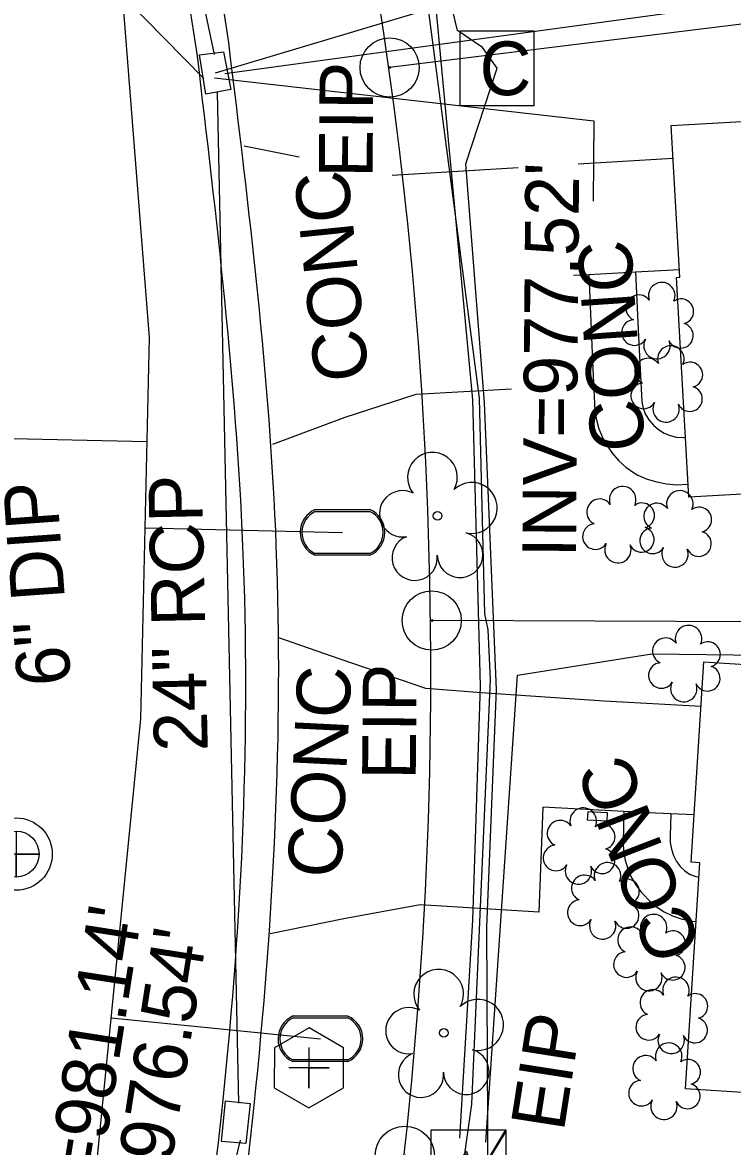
# Model space of a CAD drawing. Extents: x 1614611 to 1617571, y 898867 to 905462.
# Drawn here: x 1616421.9 to 1616474.8, y 901985 to 902068.7 of the extents above; entities that cross this region are included whole.
import ezdxf

# ---------------------------------------------------------------- set-up
doc = ezdxf.new("R2010")
doc.units = 0
for name, color, linetype in [('Exist Boundary Watershed Residential C 05', 7, 'Continuous'), ('Exist Building', 7, 'Continuous'), ('Exist Drainage Structure Drop Inlet CELL', 7, 'Continuous'), ('Exist Other Culture Area Outline', 7, 'Continuous'), ('Exist Other Culture Area Outline Text', 7, 'Continuous'), ('Exist Plan Preparation Watershed Yellow', 7, 'Continuous'), ('Exist Roads EOP Other Text', 7, 'Continuous'), ('Exist Structure Minor Catch Basin Top Elevation', 7, 'Continuous'), ('Exist Structure Minor Pipes RCP 24 Inch Invert', 7, 'Continuous'), ('Exist Utilities Sanitary Sewer UG Line Text', 7, 'Continuous'), ('Exist Utilities Telephone UG FO SUE LOS B', 7, 'Continuous'), ('Exist Utilities TV Pedestal CELL', 7, 'Continuous'), ('Exist Utilities TV UG Cable SUE LOS B', 7, 'Continuous'), ('Exist Utilities Water UG Line SUE LOS B', 7, 'Continuous'), ('Exist Vegetation Shrub CELL', 7, 'Continuous'), ('Exist Vegetation Tree CELL', 7, 'Continuous'), ('Old_Level_21', 7, 'Continuous'), ('Prop Drainage Structure Catch Basin Grate 840 03E Label', 7, 'Continuous'), ('Prop Drainage Structure Catch Basin Open Throat 4 CELL', 7, 'Continuous'), ('Prop Drainage Structure Pipe Alternate 18in Label', 7, 'Continuous'), ('Prop Drainage Structure Pipe Alternate 30in Label', 7, 'Continuous'), ('Prop Drainage Structure Pipe Stub Out CELL', 7, 'Continuous'), ('Prop Earthen Structure Head Ditch Label', 7, 'Continuous'), ('Prop Erosion Embankment Toe Protection CELL', 7, 'Continuous'), ('Prop Erosion Embankment Toe Protection Label', 7, 'Continuous'), ('Prop Erosion Embankment Toe Protection with Rip Rap 3 Detail CELL', 7, 'Continuous'), ('Prop Erosion Rip Rap Class B Label', 7, 'Continuous'), ('Prop Plan Preparation Drainage Notes Label', 7, 'Continuous'), ('Prop Plan Preparation Elevation Label', 7, 'Continuous'), ('Prop SS Transition Line', 7, 'Continuous'), ('Raster_Level_4', 7, 'Continuous'), ('Scratch_Level_1', 7, 'Continuous'), ('Scratch_Level_9', 7, 'Continuous')]:
    doc.layers.add(name, color=color, linetype=linetype)

# ---------------------------------------------------------------- blocks, each defined once
blk = doc.blocks.new('EXIST UTILITIES SANITARY SEWER MANHOLE')
at = {"layer": 'Old_Level_21'}
blk.add_lwpolyline([(0, 0.03425), (0, -0.03425), (0, 0), (0.03425, 0), (-0.03425, 0)], dxfattribs=at)
for radius in [0.05389, 0.03425]:
    blk.add_circle((0, 0), radius, dxfattribs=at)
blk = doc.blocks.new('EXIST PROPERTY IRON PIN')
at = {"layer": 'Exist Plan Preparation Watershed Yellow'}
for radius in [0.0441, 0.00141]:
    blk.add_circle((0, 0), radius, dxfattribs=at)
blk = doc.blocks.new('EXIST UTILITIES SANITARY SEWER CLEAN-OUT')
at = {"layer": 'Prop Drainage Structure Pipe Stub Out CELL'}
blk.add_line((0, 0), (0, 0), dxfattribs=at)
blk.add_lwpolyline([(-0.0516, 0.0299), (-0.0517, -0.0297), (-0.0001, -0.0596), (0.0516, -0.0299), (0.0517, 0.0297), (0.0001, 0.0596)], close=True, dxfattribs=at)
blk.add_lwpolyline([(0, 0.0302), (0, -0.0302), (0, 0), (0.0302, 0), (-0.0302, 0)], dxfattribs=at)
blk = doc.blocks.new('EXIST UTILITIES POWER TRANSFORMER')
at = {"layer": 'Prop Erosion Rip Rap Class B Label'}
blk.add_line((0, 0), (0, 0), dxfattribs=at)
blk.add_lwpolyline([(-0.0569, 0.0522), (0.0542, 0.0522), (0.0542, -0.0588), (-0.0569, -0.0588)], close=True, dxfattribs=at)
for points in [[(-0.0569, -0.0588), (-0.004, 0.0201), (0.0086, -0.0241), (0.0542, 0.0522)], [(-0.0555, -0.0588), (-0.004, 0.0159), (0.0077, -0.0278), (0.0542, 0.0491)]]:
    blk.add_lwpolyline(points, dxfattribs=at)
blk = doc.blocks.new('EXIST UTILITIES WATER METER')
at = {"layer": 'Prop SS Transition Line'}
blk.add_line((0, 0), (0, 0), dxfattribs=at)
for points in [[(-0.0408, 0.034), (0.0408, 0.034)], [(-0.0408, 0.0312), (0.0408, 0.0312)], [(0.0408, -0.0312), (-0.0413, -0.0312)], [(0.0408, -0.034), (-0.0413, -0.034)]]:
    blk.add_lwpolyline(points, dxfattribs=at)
for centre, radius, start, end in [((-0.0261, -0.0001), 0.0371, 113.178, 245.9794), ((0.0259, 0), 0.0371, 293.6483, 66.3084), ((-0.0259, -0.0001), 0.0347, 115.3009, 243.7824), ((0.0261, 0), 0.0345, 295.1272, 64.8728)]:
    blk.add_arc(centre, radius, start, end, dxfattribs=at)

msp = doc.modelspace()

# ---------------------------------------------------------------- linework, layer by layer
at = {"layer": 'Exist Boundary Watershed Residential C 05'}
msp.add_lwpolyline([(1616437.241, 902067.23), (1616435.966, 902075.619), (1616429.529, 902106.767), (1616421.436, 902145.227), (1616412.821, 902186.451), (1616404.233, 902227.126), (1616395.845, 902267.01), (1616387.691, 902305.775), (1616383.451, 902325.828)], dxfattribs=at)
msp.add_spline([(1616403.142, 901870.93), (1616413.385, 901891.845), (1616421.355, 901911.815), (1616433.371, 901951.993), (1616439.135, 901988.052), (1616440.789, 902029.724), (1616437.241, 902067.23)], degree=3, dxfattribs=at)
at = {"layer": 'Exist Building'}
msp.add_lwpolyline([(1616504.034, 902061.991), (1616505.537, 902035.279), (1616471.54, 902033.367), (1616470.62, 902049.726), (1616470.865, 902049.74), (1616470.229, 902061.048), (1616475.486, 902061.344), (1616475.54, 902060.388)], close=True, dxfattribs=at)
msp.add_lwpolyline([(1616510.197, 902017.261), (1616508.177, 901985.64), (1616476.199, 901987.683), (1616476.281, 901988.978), (1616471.285, 901989.297), (1616472.36, 902006.124), (1616471.704, 902006.166), (1616472.658, 902021.104), (1616499.409, 902019.395)], dxfattribs=at)
at = {"layer": 'Exist Other Culture Area Outline'}
for points in [[(1616467.552, 902050.129), (1616467.778, 902045.32), (1616468.03, 902040.457), (1616468.135, 902039.974), (1616468.317, 902039.515), (1616468.57, 902039.091), (1616468.889, 902038.713), (1616469.263, 902038.391), (1616469.685, 902038.134), (1616470.143, 902037.949), (1616470.625, 902037.839), (1616471.107, 902037.809), (1616471.289, 902037.817)], [(1616464.074, 902049.943), (1616464.369, 902042.925), (1616464.536, 902039.819), (1616464.647, 902039.125), (1616464.836, 902038.447), (1616465.1, 902037.795), (1616465.436, 902037.176), (1616465.84, 902036.6), (1616466.306, 902036.073), (1616466.828, 902035.602), (1616467.4, 902035.194), (1616467.735, 902034.996), (1616468.426, 902034.705), (1616469.144, 902034.489), (1616469.88, 902034.349), (1616470.626, 902034.289), (1616471.486, 902034.323)], [(1616466.681, 902009.958), (1616466.644, 902007.647), (1616466.676, 902006.978), (1616466.788, 902006.318), (1616466.977, 902005.676), (1616467.242, 902005.061), (1616467.578, 902004.482), (1616467.981, 902003.947), (1616468.12, 902003.79), (1616468.592, 902003.294), (1616469.119, 902002.857), (1616469.693, 902002.484), (1616470.307, 902002.18), (1616470.952, 902001.95), (1616471.62, 902001.797), (1616471.755, 902001.776), (1616472.081, 902001.748)], [(1616470.191, 902009.776), (1616470.147, 902008.134), (1616470.15, 902007.634), (1616470.232, 902007.14), (1616470.392, 902006.666), (1616470.625, 902006.224), (1616470.925, 902005.824), (1616471.226, 902005.527), (1616471.584, 902005.294), (1616471.98, 902005.132), (1616472.293, 902005.068)]]:
    msp.add_lwpolyline(points, dxfattribs=at)
at = {"layer": 'Exist Utilities Telephone UG FO SUE LOS B'}
msp.add_lwpolyline([(1616404.066, 901801.19), (1616405.183, 901802.348), (1616409.015, 901827.116), (1616413.015, 901844.471), (1616417.592, 901857.479), (1616419.975, 901858.52), (1616420.384, 901859.301), (1616420.063, 901863.222), (1616425.516, 901876.625), (1616432.623, 901893.45), (1616436.62, 901902.214), (1616447.41, 901937.917), (1616451.473, 901942.162), (1616451.671, 901943.076), (1616450.182, 901945.261), (1616452.643, 901960.196), (1616453.868, 901977.593), (1616455.367, 901988.16), (1616456.764, 902019.785), (1616456.582, 902023.478), (1616456.334, 902024.672), (1616455.931, 902040.742), (1616451.443, 902075.024)], dxfattribs=at)
at = {"layer": 'Exist Utilities TV Pedestal CELL'}
msp.add_line((1616457.243, 902065.295), (1616457.243, 902065.295), dxfattribs=at)
msp.add_lwpolyline([(1616454.468, 902062.52), (1616460.018, 902062.52), (1616460.018, 902068.07), (1616454.468, 902068.07), (1616454.468, 902062.52)], dxfattribs=at)
at = {"layer": 'Exist Utilities TV UG Cable SUE LOS B'}
for points in [[(1616457.243, 902065.295), (1616456.167, 902066.855), (1616454.297, 902068.104), (1616452.831, 902074.241), (1616452.82, 902103.16)], [(1616423.307, 901860.195), (1616421.035, 901863.624), (1616426.241, 901876.389), (1616433.091, 901892.926), (1616437.599, 901901.772), (1616438.32, 901902.665), (1616448.536, 901937.63), (1616453.419, 901959.852), (1616455.53, 901976.747), (1616457.243, 901978.856), (1616456.999, 901980.071), (1616456.57, 901981.798), (1616456.486, 902001.336), (1616457.199, 902019.032), (1616456.304, 902040.378), (1616454.923, 902058.172), (1616457.243, 902065.295)]]:
    msp.add_lwpolyline(points, dxfattribs=at)
at = {"layer": 'Exist Utilities Water UG Line SUE LOS B'}
for p, q in [((1616431.169, 902037.468), (1616407.628, 902038.002)), ((1616431.023, 902031.066), (1616445.725, 902030.733)), ((1616428.485, 901994.572), (1616444.078, 901993.021))]:
    msp.add_line(p, q, dxfattribs=at)
msp.add_lwpolyline([(1616387.062, 901856.442), (1616402.16, 901887.526), (1616412.921, 901915.139), (1616425.66, 901966.176), (1616430.701, 902016.844), (1616431.345, 902045.247), (1616429.197, 902072.396), (1616417.907, 902130.933), (1616404.63, 902193.297), (1616390.922, 902255.687), (1616390.447, 902257.774)], dxfattribs=at)
at = {"layer": 'Exist Vegetation Shrub CELL'}
for p, q in [((1616469.288, 902046.324), (1616469.288, 902046.324)), ((1616469.966, 902041.608), (1616469.966, 902041.608)), ((1616466.374, 902031.128), (1616466.374, 902031.128)), ((1616470.634, 902030.815), (1616470.634, 902030.815)), ((1616471.286, 902020.782), (1616471.286, 902020.782)), ((1616463.434, 902007.193), (1616463.434, 902007.193)), ((1616465.243, 902003.117), (1616465.243, 902003.117)), ((1616468.684, 901999.259), (1616468.684, 901999.259)), ((1616470.347, 901994.588), (1616470.347, 901994.588)), ((1616469.806, 901989.681), (1616469.806, 901989.681))]:
    msp.add_line(p, q, dxfattribs=at)
for centre, radius, start, end in [((1616469.517, 902048.365), 0.99, 334.83907, 200.47174), ((1616467.805, 902047.451), 0.968, 35.89076, 245.42165), ((1616470.96, 902047.193), 0.929, 284.45672, 126.08612), ((1616467.487, 902045.62), 0.955, 95.10992, 327.95341), ((1616470.925, 902045.395), 0.937, 204.99133, 73.46012), ((1616469.159, 902044.641), 0.984, 151.27966, 21.38702), ((1616470.195, 902043.649), 0.99, 334.83907, 200.47174), ((1616468.483, 902042.735), 0.968, 35.89076, 245.42165), ((1616471.638, 902042.477), 0.929, 284.45672, 126.08612), ((1616468.166, 902040.904), 0.955, 95.10992, 327.95341), ((1616471.603, 902040.679), 0.937, 204.99133, 73.46012), ((1616469.838, 902039.924), 0.984, 151.27966, 21.38702), ((1616466.603, 902033.168), 0.99, 334.83907, 200.47174), ((1616470.862, 902032.855), 0.99, 334.83907, 200.47174), ((1616464.892, 902032.255), 0.968, 35.89076, 245.42165), ((1616468.046, 902031.997), 0.929, 284.45672, 126.08612), ((1616469.151, 902031.942), 0.968, 35.89076, 245.42165), ((1616472.306, 902031.684), 0.929, 284.45672, 126.08612), ((1616464.574, 902030.424), 0.955, 95.10992, 327.95341), ((1616468.012, 902030.199), 0.937, 204.99133, 73.46012), ((1616468.833, 902030.11), 0.955, 95.10992, 327.95341), ((1616472.271, 902029.886), 0.937, 204.99133, 73.46012), ((1616466.246, 902029.444), 0.984, 151.27966, 21.38702), ((1616470.505, 902029.131), 0.984, 151.27966, 21.38702), ((1616471.515, 902022.823), 0.99, 334.83907, 200.47174), ((1616469.803, 902021.909), 0.968, 35.89076, 245.42165), ((1616472.958, 902021.651), 0.929, 284.45672, 126.08612), ((1616469.486, 902020.078), 0.955, 95.10992, 327.95341), ((1616472.923, 902019.853), 0.937, 204.99133, 73.46012), ((1616471.158, 902019.098), 0.984, 151.27966, 21.38702), ((1616463.663, 902009.234), 0.99, 334.83907, 200.47174), ((1616461.952, 902008.32), 0.968, 35.89076, 245.42165), ((1616465.106, 902008.062), 0.929, 284.45672, 126.08612), ((1616461.634, 902006.489), 0.955, 95.10992, 327.95341), ((1616465.072, 902006.264), 0.937, 204.99133, 73.46012), ((1616463.306, 902005.51), 0.984, 151.27966, 21.38702), ((1616465.471, 902005.158), 0.99, 334.83907, 200.47174), ((1616463.76, 902004.244), 0.968, 35.89076, 245.42165), ((1616466.915, 902003.986), 0.929, 284.45672, 126.08612), ((1616463.442, 902002.413), 0.955, 95.10992, 327.95341), ((1616466.88, 902002.188), 0.937, 204.99133, 73.46012), ((1616465.114, 902001.433), 0.984, 151.27966, 21.38702), ((1616468.913, 902001.3), 0.99, 334.83907, 200.47174), ((1616467.201, 902000.386), 0.968, 35.89076, 245.42165), ((1616470.356, 902000.128), 0.929, 284.45672, 126.08612), ((1616466.884, 901998.555), 0.955, 95.10992, 327.95341), ((1616470.321, 901998.33), 0.937, 204.99133, 73.46012), ((1616468.556, 901997.575), 0.984, 151.27966, 21.38702), ((1616470.575, 901996.628), 0.99, 334.83907, 200.47174), ((1616468.864, 901995.715), 0.968, 35.89076, 245.42165), ((1616472.019, 901995.457), 0.929, 284.45672, 126.08612), ((1616468.546, 901993.883), 0.955, 95.10992, 327.95341), ((1616471.984, 901993.659), 0.937, 204.99133, 73.46012), ((1616470.218, 901992.904), 0.984, 151.27966, 21.38702), ((1616470.034, 901991.721), 0.99, 334.83907, 200.47174), ((1616468.323, 901990.807), 0.968, 35.89076, 245.42165), ((1616471.478, 901990.549), 0.929, 284.45672, 126.08612), ((1616468.005, 901988.976), 0.955, 95.10992, 327.95341), ((1616471.443, 901988.752), 0.937, 204.99133, 73.46012), ((1616469.677, 901987.997), 0.984, 151.27966, 21.38702)]:
    msp.add_arc(centre, radius, start, end, dxfattribs=at)
at = {"layer": 'Exist Vegetation Tree CELL'}
for p, q in [((1616452.808, 902031.967), (1616452.808, 902031.967)), ((1616453.273, 901993.469), (1616453.273, 901993.469))]:
    msp.add_line(p, q, dxfattribs=at)
for centre in [(1616452.808, 902031.967), (1616453.273, 901993.469)]:
    msp.add_circle(centre, 0.326, dxfattribs=at)
for centre, radius, start, end in [((1616452.423, 902034.841), 1.856, 330.16508, 219.71335), ((1616455.357, 902032.556), 1.899, 257.1011, 134.19993), ((1616450.202, 902032.121), 1.727, 62.66361, 279.3457), ((1616451.104, 902028.846), 1.689, 111.56708, 6.23104), ((1616454.481, 902029.068), 1.698, 181.28216, 74.55999), ((1616452.888, 901996.342), 1.856, 330.16508, 219.71335), ((1616455.822, 901994.058), 1.899, 257.1011, 134.19993), ((1616450.668, 901993.623), 1.727, 62.66361, 279.3457), ((1616451.569, 901990.348), 1.689, 111.56708, 6.23104), ((1616454.946, 901990.57), 1.698, 181.28216, 74.55999)]:
    msp.add_arc(centre, radius, start, end, dxfattribs=at)
at = {"layer": 'Prop Drainage Structure Catch Basin Grate 840 03E Label'}
for points in [[(1616454.459, 901985.624), (1616455.446, 902001.848), (1616456.006, 902019.307), (1616455.441, 902040.612), (1616452.267, 902074.596), (1616447.794, 902107.722), (1616449.973, 902108.838), (1616482.132, 902113.842), (1616487.315, 902107.556)], [(1616456.403, 901985.328), (1616458.761, 902020.096), (1616468.778, 902021.69), (1616491.144, 902021.411), (1616492.144, 902018.822)]]:
    msp.add_lwpolyline(points, dxfattribs=at)
at = {"layer": 'Prop Drainage Structure Catch Basin Open Throat 4 CELL'}
for points in [[(1616437.391, 902063.707), (1616435.546, 902063.38), (1616435.074, 902066.293), (1616436.851, 902066.524), (1616437.391, 902063.707)], [(1616438.515, 901985.22), (1616436.714, 901985.376), (1616437.009, 901988.407), (1616438.834, 901988.197), (1616438.515, 901985.22)]]:
    msp.add_lwpolyline(points, dxfattribs=at)
at = {"layer": 'Prop Drainage Structure Pipe Alternate 18in Label'}
msp.add_line((1616544.457, 902079.578), (1616436.941, 902064.874), dxfattribs=at)
at = {"layer": 'Prop Drainage Structure Pipe Alternate 30in Label'}
for p, q in [((1616579.449, 902081.427), (1616449.232, 902065.348)), ((1616591.58, 902023.616), (1616452.369, 902024.175))]:
    msp.add_line(p, q, dxfattribs=at)
at = {"layer": 'Prop Earthen Structure Head Ditch Label'}
msp.add_arc((1616126.099, 902020.281), 326.203, 330.93872, 10.91752, dxfattribs=at)
at = {"layer": 'Prop Erosion Embankment Toe Protection CELL'}
msp.add_lwpolyline([(1616465.419, 902009.227), (1616463.991, 902009.305), (1616464.023, 902009.954), (1616465.451, 902009.876)], close=True, dxfattribs=at)
at = {"layer": 'Prop Erosion Embankment Toe Protection Label'}
for p, q in [((1616438, 901988.234), (1616436.393, 902063.483)), ((1616438.086, 901985.474), (1616420.446, 901912.025))]:
    msp.add_line(p, q, dxfattribs=at)
at = {"layer": 'Prop Erosion Embankment Toe Protection with Rip Rap 3 Detail CELL'}
for p, q in [((1616436.174, 902066.313), (1616410.563, 902190.405)), ((1616435.39, 902064.539), (1616406.621, 902093.746))]:
    msp.add_line(p, q, dxfattribs=at)
at = {"layer": 'Prop Plan Preparation Drainage Notes Label'}
msp.add_lwpolyline([(1616436.26, 902064.971), (1616461.444, 902072.518), (1616461.493, 902078.518)], dxfattribs=at)
at = {"layer": 'Prop Plan Preparation Elevation Label'}
msp.add_lwpolyline([(1616436.173, 902064.598), (1616464.458, 902061.395), (1616464.409, 902055.395)], dxfattribs=at)
at = {"layer": 'Scratch_Level_1'}
for points in [[(1616442.482, 902058.687), (1616438.384, 902059.502)], [(1616470.367, 902058.59), (1616463.281, 902058.147)], [(1616458.822, 902057.876), (1616449.416, 902057.306)], [(1616462.934, 902049.883), (1616464.074, 902049.943), (1616467.552, 902050.129), (1616470.833, 902050.305)], [(1616440.532, 902037.297), (1616445.92, 902039.307), (1616451.206, 902041.035), (1616458.317, 902041.43)], [(1616472.445, 902017.764), (1616465.229, 902018.162), (1616456.091, 902018.788), (1616451.925, 902019.116), (1616445.55, 902021.294), (1616440.908, 902022.909)], [(1616471.929, 902009.692), (1616470.191, 902009.776), (1616469.055, 902009.831), (1616466.681, 902009.958), (1616460.654, 902010.282), (1616460.354, 902002.464), (1616451.519, 902003.009), (1616445.82, 902001.95), (1616440.342, 902000.845)]]:
    msp.add_lwpolyline(points, dxfattribs=at)
at = {"layer": 'Scratch_Level_9'}
msp.add_lwpolyline([(1616434.891, 902066.362), (1616433.511, 902075.134), (1616427.005, 902106.366), (1616418.897, 902144.808), (1616410.397, 902185.957), (1616401.753, 902226.574), (1616393.457, 902265.918), (1616385.184, 902305.307), (1616381.059, 902325.22)], dxfattribs=at)
msp.add_spline([(1616401.72, 901873.638), (1616410.999, 901892.827), (1616419.064, 901912.725), (1616430.933, 901952.504), (1616436.821, 901988.482), (1616438.3, 902029.711), (1616434.891, 902066.362)], degree=3, dxfattribs=at)

# ---------------------------------------------------------------- block references
at = {"layer": 'Exist Plan Preparation Watershed Yellow', "xscale": 50, "yscale": 50}
for p in [(1616449.232, 902065.354), (1616452.369, 902024.175), (1616450.369, 901984.309)]:
    msp.add_blockref('EXIST PROPERTY IRON PIN', p, dxfattribs=at)
at = {"layer": 'Old_Level_21', "xscale": 50, "yscale": 50}
msp.add_blockref('EXIST UTILITIES SANITARY SEWER MANHOLE', (1616421.394, 902006.78), dxfattribs=at)
at = {"layer": 'Prop Drainage Structure Pipe Stub Out CELL', "xscale": 50, "yscale": 50}
msp.add_blockref('EXIST UTILITIES SANITARY SEWER CLEAN-OUT', (1616443.222, 901990.858), dxfattribs=at)
at = {"layer": 'Prop Erosion Rip Rap Class B Label', "xscale": 50, "yscale": 50}
msp.add_blockref('EXIST UTILITIES POWER TRANSFORMER', (1616455.175, 901983.642), dxfattribs=at)
at = {"layer": 'Prop SS Transition Line', "xscale": 50, "yscale": 50}
for p in [(1616445.725, 902030.733), (1616444.078, 901993.021)]:
    msp.add_blockref('EXIST UTILITIES WATER METER', p, dxfattribs=at)

# ---------------------------------------------------------------- texts
at = {"layer": 'Exist Drainage Structure Drop Inlet CELL'}
for rotation, p in [(89.53333, (1616447.956, 902057.137)), (89.53333, (1616451.179, 902012.308)), (81.13577, (1616462.205, 901986.047))]:
    msp.add_text('EIP', height=4, rotation=rotation, dxfattribs=at).set_placement(p)
at = {"layer": 'Exist Other Culture Area Outline Text'}
for rotation, p in [(93.87351, (1616468.273, 902036.891)), (111.0145, (1616472.526, 901999.742))]:
    msp.add_text('CONC', height=4, rotation=rotation, dxfattribs=at).set_placement(p)
at = {"layer": 'Exist Roads EOP Other Text'}
for rotation, p in [(95.81823, (1616447.689, 902042.169)), (87.14436, (1616445.611, 902004.95))]:
    msp.add_text('CONC', height=4, rotation=rotation, dxfattribs=at).set_placement(p)
at = {"layer": 'Exist Structure Minor Catch Basin Top Elevation'}
msp.add_text("TOP=981.14'", height=4, rotation=81.13577, dxfattribs=at).set_placement((1616425.947, 901971.421))
at = {"layer": 'Exist Structure Minor Pipes RCP 24 Inch Invert'}
for s, rotation, p in [("INV=977.52'", 89.53333, (1616463.121, 902028.858)), ("INV=976.54'", 81.13577, (1616431.119, 901971.82))]:
    msp.add_text(s, height=4, rotation=rotation, dxfattribs=at).set_placement(p)
at = {"layer": 'Exist Utilities Sanitary Sewer UG Line Text'}
msp.add_text('6" DIP', height=4, rotation=94.10486, dxfattribs=at).set_placement((1616425.49, 902019.439))
at = {"layer": 'Exist Utilities TV Pedestal CELL'}
msp.add_text('C', height=4, dxfattribs=at).set_placement((1616455.936, 902063.295))
at = {"layer": 'Raster_Level_4'}
msp.add_text('24" RCP', height=4, rotation=91.22341, dxfattribs=at).set_placement((1616435.684, 902014.45))

doc.saveas('drawing.dxf')
